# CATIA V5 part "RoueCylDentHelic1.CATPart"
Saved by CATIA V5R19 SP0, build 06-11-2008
Part number: Roue Cyl Denture Hélicoïdale
Bounding box of the stored display mesh (mm): x -74.504 to 74.497, y -74.496 to 74.494, z -20.617 to 50
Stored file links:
  G:\EU_thinkMotion\CFAO_2010\MMS_groupe2\MMS_groupe2\OK\melguidj\cfao_elguidj_2AMMSgrB\Modèle 3D\RoueCylDentHelic1.CATPart
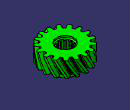
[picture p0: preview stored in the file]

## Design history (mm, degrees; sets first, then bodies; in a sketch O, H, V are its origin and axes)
External parameters (linked from other documents)
  External.Module = 7 mm
  External.Z = 17
  External.DiamPrimitif = 137.4094 mm {= External.ModuleApparent*External.Z}
  External.AnglePression = 20 deg
  External.x = 0
  External.DeportDenture = 0 mm {= External.x *External.ModuleApparent}
  External.DiamBase = 129.1226 mm {= External.DiamPrimitif *cos(External.AnglePression )}
  External.DiamPied = 119.9094 mm {= External.DiamPrimitif -2.5*External.Module +2*External.DeportDenture}
  External.DiamTete = 149 mm
  External.PhiPrimitif = 0.854 deg {= atan((sin(External.ThetaPrimitif*1rad)-External.ThetaPrimitif*cos(External.ThetaPrimitif*1rad))/(cos(External.ThetaPrimitif*1rad)+External.ThetaPrimitif*sin(External.ThetaPrimitif*1rad)))}
  External.PhiTete = 3.058 deg {= atan((sin(External.ThetaTete*1rad)-External.ThetaTete*cos(External.ThetaTete*1rad))/(cos(External.ThetaTete*1rad)+External.ThetaTete*sin(External.ThetaTete*1rad)))}
  External.PhiSymetrie = 5.2941 deg {= 180*1 deg/(2*External.Z )}
  External.CongePied = 2.66 mm {= 0.38*External.Module}
  External.AlphaCopie = 21.1765 deg {= 360*1 deg/External.Z}
  External.AlphaSymetrieCopie = 10.5882 deg {= External.AlphaCopie /2}
  External.LargeurDenture = 50 mm {= 50mm}
  External.ThetaPrimitif = 0.36397 {= sqrt(abs((External.DiamPrimitif*External.DiamPrimitif)/(External.DiamBase *External.DiamBase )-1))}
  External.ThetaTete = 0.575832 {= sqrt(abs((External.DiamTete*External.DiamTete)/(External.DiamBase *External.DiamBase )-1) )}
  External.Di = 133.266 mm {= (External.DiamBase +External.DiamPrimitif )/2}
  External.Thetai = 0.255358 {= sqrt(abs((External.Di*External.Di)/(External.DiamBase*External.DiamBase)-1))}
  External.Phii = 0.3061 deg {= atan((sin(External.Thetai*1rad)-External.Thetai*cos(External.Thetai*1rad))/(cos(External.Thetai*1rad)+External.Thetai*sin(External.Thetai*1rad)))}
  External.Dj = 143.2047 mm {= (External.DiamTete+External.DiamPrimitif)/2}
  External.Thetaj = 0.479598 {= sqrt(abs((External.Dj*External.Dj)/(External.DiamBase*External.DiamBase)-1))}
  External.Phij = 1.8567 deg {= atan((sin(External.Thetaj*1rad)-External.Thetaj*cos(External.Thetaj*1rad))/(cos(External.Thetaj*1rad)+External.Thetaj*sin(External.Thetaj*1rad)))}
  External.Dk = 131.1943 mm {= (External.Di+External.DiamBase)/2}
  External.Thetak = 0.179851 {= sqrt(abs((External.Dk*External.Dk)/(External.DiamBase*External.DiamBase)-1))}
  External.Phik = 0.109 deg {= atan((sin(External.Thetak*1rad)-External.Thetak*cos(External.Thetak*1rad))/(cos(External.Thetak*1rad)+External.Thetak*sin(External.Thetak*1rad)))}
  External.Dl = 135.3377 mm {= (External.DiamPrimitif+External.Di)/2}
  External.Thetal = 0.31398 {= sqrt(abs((External.Dl*External.Dl)/(External.DiamBase*External.DiamBase)-1))}
  External.Phil = 0.5585 deg {= atan((sin(External.Thetal*1rad)-External.Thetal*cos(External.Thetal*1rad))/(cos(External.Thetal*1rad)+External.Thetal*sin(External.Thetal*1rad)))}
  External.Dm = 140.307 mm {= (External.Dj+External.DiamPrimitif)/2}
  External.Thetam = 0.425136 {= sqrt(abs((External.Dm*External.Dm)/(External.DiamBase*External.DiamBase)-1))}
  External.Phim = 1.3264 deg {= atan((sin(External.Thetam*1rad)-External.Thetam*cos(External.Thetam*1rad))/(cos(External.Thetam*1rad)+External.Thetam*sin(External.Thetam*1rad)))}
  External.Dn = 146.1023 mm {= (External.DiamTete+External.Dj)/2}
  External.Thetan = 0.529429 {= sqrt(abs((External.Dn*External.Dn)/(External.DiamBase*External.DiamBase)-1))}
  External.Phin = 2.436 deg {= atan((sin(External.Thetan*1rad)-External.Thetan*cos(External.Thetan*1rad))/(cos(External.Thetan*1rad)+External.Thetan*sin(External.Thetan*1rad)))}
  External.AngleHelice = 30 deg
  External.ModuleApparent = 8.0829 mm {= External.Module /cos(External.AngleHelice )}
  External.SensDenture = -1
  External.LargeurDent = 45 mm {= round(PI*External.Module /sin(External.AngleHelice )/1mm)*1mm+1mm}
Body1 (main body)
  Sketch1 "EsquisseDent" on xy-plane, origin (0, 0, 0), H (1, 0, 0), V (0, 1, 0)
    construction circle A1 centre (0, 0) radius 68.7047
    construction circle A2 centre (0, 0) radius 64.5613
    construction circle A3 centre (0, 0) radius 59.9547
    construction circle A4 centre (0, 0) radius 74.5
    point P1 (64.5613, 0)
    construction line L1 (64.5613, 0) -> (0, 0)
    point P2 (68.6971, 1.024)
    construction line L2 (68.6971, 1.024) -> (0, 0)
    point P3 (74.3939, 3.9744)
    construction line L3 (74.3939, 3.9744) -> (0, 0)
    construction line L4 (64.5613, 0) -> (64.5613, 3.9367)
    point P4 (64.5613, 0)
    point P6 (60.4255, 1.024)
    construction line L5 (74.3939, 3.9744) -> (68.6971, 1.024)
    point P7 (71.5455, 2.4992)
    point P8 (57.5771, 2.4992)
    spline S1 through (57.5771, 2.4992) (60.4255, 1.024) (64.5613, 0) (65.597, 0.1248) (66.632, 0.356) (67.6656, 0.6596) (68.6971, 1.024) (70.1347, 1.6239) (71.5648, 2.3199) (72.9852, 3.1049) (74.3939, 3.9744)
    construction line L6 (0, 0) -> (5.2441, 0.5649)
    spline S2 through (56.7885, 9.82) (59.2574, 11.868) (63.0802, 13.7493) (64.1188, 13.8479) (65.1793, 13.8424) (66.2538, 13.7659) (67.3392, 13.6296) (68.8717, 13.3496) (70.4171, 12.9741) (71.9721, 12.5096) (73.5337, 11.9601)
    arc A5 centre (62.5641, -2.5174) radius 2.66 from (63.0483, 0.0982) to (59.9062, -2.4104) ccw
    point P11 (59.9062, -2.4104)
    arc A6 centre (0, 0) radius 74.5 from (74.3939, 3.9744) to (73.5337, 11.9601) ccw
    point P13 (73.5337, 11.9601)
    arc A7 centre (60.5927, 15.7836) radius 2.66 from (58.0186, 15.113) to (61.6229, 13.3311) ccw
    point P15 (58.0186, 15.113)
    construction line L7 (0, 0) -> (4.1018, 1.2334)
    construction line L8 (0, 0) -> (5.1105, -0.3968)
    point P19 (57.415, 17.265)
    arc A8 centre (0, 0) radius 59.9547 from (58.0186, 15.113) to (57.415, 17.265) ccw
    point P20 (59.7747, -4.6416)
    arc A9 centre (0, 0) radius 59.9547 from (59.7747, -4.6416) to (59.9062, -2.4104) ccw
    line L9 (57.415, 17.265) -> (0, 0)
    line L10 (59.7747, -4.6416) -> (0, 0)
    construction circle A10 centre (0, 0) radius 66.633
    construction line L11 (0, 0) -> (2.5698, 0.0137)
    point P22 (66.632, 0.356)
    construction circle A11 centre (0, 0) radius 71.6023
    construction line L12 (0, 0) -> (4.017, 0.1302)
    point P24 (71.5648, 2.3199)
    point P25 (71.5648, 2.3199)
    point P26 (70.4171, 12.9741)
    point P27 (65.1793, 13.8424)
    construction circle A12 centre (0, 0) radius 65.5971
    construction line L13 (0, 0) -> (48.2618, 0.0918)
    point P29 (64.1188, 13.8479)
    construction line L14 (0, 0) -> (63.6105, 6.852)
    point P31 (65.597, 0.1248)
    construction circle A13 centre (0, 0) radius 67.6688
    construction line L15 (0, 0) -> (57.3607, 0.5591)
    point P33 (67.6656, 0.6596)
    point P34 (66.2538, 13.7659)
    construction circle A14 centre (0, 0) radius 70.1535
    construction line L16 (0, 0) -> (65.6931, 1.5211)
    point P36 (70.1347, 1.6239)
    point P37 (68.8717, 13.3496)
    construction circle A15 centre (0, 0) radius 73.0512
    axis line L17 (0, 0) -> (59.2973, 2.5226)
    point P39 (71.9721, 12.5096)
    point P40 (72.9852, 3.1049)
    point P42 (57.5771, 2.4992)
    point P43 (60.4255, 1.024)
    point P44 (64.5613, 0)
    point P45 (68.6971, 1.024)
    point P46 (74.3939, 3.9744)
    point P47 (73.5337, 11.9601)
    point P48 (56.7885, 9.82)
    point P49 (67.3392, 13.6296)
    point P50 (63.0802, 13.7493)
    point P51 (59.2574, 11.868)
    point P52 (66.632, 0.356)
    point P53 (71.5648, 2.3199)
    point P54 (65.1793, 13.8424)
    point P55 (70.4171, 12.9741)
    point P56 (65.597, 0.1248)
    point P57 (64.1188, 13.8479)
    point P58 (67.6656, 0.6596)
    point P59 (66.2538, 13.7659)
    point P60 (70.1347, 1.6239)
    point P61 (68.8717, 13.3496)
    point P62 (72.9852, 3.1049)
    point P63 (71.9721, 12.5096)
    radius A1 = 68.7047 {= External.DiamPrimitif /2}
    radius A2 = 64.5613 {= External.DiamBase /2}
    radius A3 = 59.9547 {= External.DiamPied /2}
    radius A4 = 74.5 {= External.DiamTete /2}
    angle L2 L1 = 0.854 {= External.PhiPrimitif}
    angle L3 L1 = 3.058 {= External.PhiTete}
    angle L4 L1 = 90
    radius A5 = 2.66 {= External.CongePied}
    radius A7 = 2.66 {= External.CongePied}
    angle L7 L6 = 10.5882 {= External.AlphaSymetrieCopie}
    angle L2 L6 = 5.2941 {= External.PhiSymetrie}
    radius A10 = 66.633 {= External.Di /2}
    angle L11 L1 = 0.3061 {= External.Phii}
    radius A11 = 71.6023 {= External.Dj /2}
    angle L12 L1 = 1.8567 {= External.Phij}
    radius A12 = 65.5971 {= External.Dk/2}
    angle L13 L1 = 0.109 {= External.Phik}
    angle L14 L2 = 5.2941 {= External.PhiSymetrie}
    radius A13 = 67.6688 {= External.Dl /2}
    angle L15 L1 = 0.5585 {= External.Phil}
    radius A14 = 70.1535 {= External.Dm /2}
    angle L16 L1 = 1.3264 {= External.Phim}
    radius A15 = 73.0512 {= External.Dn/2}
    angle L17 L1 = 2.436 {= External.Phin}
    coincidence: P1 A2, P1 H, P2 A1, P3 A4, P4 A2, P7 L5, P42 P8, P43 P6, P44 P1, P45 L5, P45 L2, P46 L5, P46 L3, P11 A3, P47 P13, P15 A3, P19 L7, P19 A3, P20 L8, P20 A3, P3 P46, P22 L11, P22 A10, P52 P22, P24 L12, P24 A11, P53 P24, P25 P53, P54 P27, P55 P26, P31 L13, P31 A12, P56 P31, P57 P29, P33 L15, P33 A13, P58 P33, P59 P34, P36 L16, P36 A14, P60 P36, P61 P37, P40 L17, P40 A15, P62 P40, P63 P39, O L9, O L10
    horizontal: L1 H
    tangency: L4 A2, A5 A3, A5 S1, A7 A3, A7 S2, A8 A5, A9 A5
    symmetry: P6 P2 L4, P8 P7 L4, P46 P47 L6, P42 P48 L6, P45 P49 L6, P44 P50 L6, P43 P51 L6, L8 L7 L6, P26 P25 L6, P27 P22 L6, P29 P31 L14, P34 P33 L14, P37 P36 L14, P39 P40 L14
    midpoint: P7 L5
    parallelism: L9 L7, L10 L8
    concentricity: A10 A2, A11 A1
  Translate1: ToTransfor Sketch1, Direction (0, 0, 1), Length 50 {= External.LargeurDenture}
  Rotate1: ToTransfor Translate1, Axis Z axis, Angle -22.7906 {= External.SensDenture *atan(2*External.LargeurDenture/External.DiamPrimitif*tan(External.AngleHelice))}
  Translate2: ToTransfor Sketch1, Direction (0, 0, 1), Length 25 {= External.LargeurDenture/2}
  Rotate2: ToTransfor Translate2, Axis Z axis, Angle -11.8644 {= External.SensDenture *atan(External.LargeurDenture/(External.DiamPrimitif)*tan(External.AngleHelice))}
  Translate3: ToTransfor Sketch1, Direction (0, 0, 1), Length 37.5 {= 3/4*External.LargeurDenture}
  Rotate3: ToTransfor Translate3, Axis Z axis, Angle -17.491 {= External.SensDenture*atan(3*External.LargeurDenture/(2*External.DiamPrimitif)*tan(External.AngleHelice))}
  Translate4: ToTransfor Sketch1, Direction (0, 0, 1), Length 12.5 {= External.LargeurDenture/4}
  Rotate4: ToTransfor Translate4, Axis Z axis, Angle -5.9965 {= External.SensDenture*atan(External.LargeurDenture/(2*External.DiamPrimitif)*tan(External.AngleHelice))}
  Loft1: solid, Sections (Sketch1; Rotate4; Rotate2; Rotate3; Rotate1)
  CircPattern1: of the body so far, instances 17 {= External.Z}, angular step 21.1765 {= External.AlphaCopie}, axis from Z axis
  Plane1: type Offset, RefPlane xy-plane, Offset 50 {= External.LargeurDenture}, reversed
  Sketch2 on Plane1, origin (0, 0, -50), H (1, 0, 0), V (0, 1, 0)
    circle A1 centre (0, 0) radius 29
    radius A1 = 29 {= int(External.DiamPied/(4mm))*1mm}
  Pocket1: profile Sketch2, direction (0, 0, 1), length 150 {= 3*External.LargeurDenture}
  DatumCurve1
  DatumCurve2
  Plane2: stored without definition
  Plane3: stored without definition
  Sketch3 on yz-plane, origin (0, 0, 0), H (0, 1, 0), V (0, 0, 1)
    point P1 (29, 0)
    line L1 (29, 0) -> (42.5, 0)
    line L2 (42.5, 0) -> (42.5, -20.6171)
    line L3 (42.5, -20.6171) -> (29, -20.6171)
    point P3 (42.5, -20.6171)
    point P5 (42.5, -20.6171)
    reference intersected line E1 (74.5, 0) -> (-59.9547, 0) from face of CircPattern1
    line L4 (29, -20.6171) -> (29, 0)
    point P6 (29, 0)
    horizontal: L1 H, L3 H
    vertical: L2 V, L4 V
    fix: P5, P6
    coincidence: P3 P5, L1 E1, P1 P6
  Shaft1: profile Sketch3, axis edge of DatumCurve2, angle 360
  DatumCurve3
  DatumCurve4
  DatumSurface1
  DatumCurve5
  Plane4: stored without definition
  DatumCurve6 to DatumCurve9
  Sketch4 on zx-plane, origin (0, 0, 0), H (-1, 0, 0), V (0, 0, 1)
    point P1 (29, 45)
    line L1 (29, 45) -> (25, 42.6906)
    line L2 (25, 42.6906) -> (25, -13.6889)
    line L3 (25, -13.6889) -> (29, -20.6171)
    point P4 (29, -20.6171)
    line L4 (29, -20.6171) -> (29, 45)
    point P5 (29, 0)
    reference intersected line E1 through (0, -20.6171) direction (1, 0) from face of Shaft1 from Sketch3.L3
    reference projected line E2 (0, 412.703) -> (0, -326.9047) from edge of DatumCurve8
    reference intersected line E3 (-70.9575, 50) -> (65.4965, 50) from face of CircPattern1
    distance L2 E2 = 25
    angle L1 L4 = 60
    angle L3 L4 = 30
    distance P1 E3 = 5
    vertical: L4 V, L2 V
    fix: P5
    coincidence: P5 L4, P4 E1
  Shaft2: profile Sketch4, axis edge of DatumCurve9, angle 360
  Sketch5 on xy-plane, origin (0, 0, 0), H (1, 0, 0), V (0, 1, 0)
    circle A1 centre (0, 0) radius 25
    point P1 (-12.9191, 21.4032)
    point P2 (-12.9191, 21.4032)
    arc A2 centre (0, 0) radius 20.1556 from (19.3636, 5.5947) to (18.4145, 8.195) ccw
    point P3 (19.3636, 5.5947)
    point P4 (18.4145, 8.195)
    arc A3 centre (0, 0) radius 20.1556 from (19.9475, 2.8889) to (19.3636, 5.5947) ccw
    point P5 (19.9475, 2.8889)
    point P6 (19.3636, 5.5947)
    line L1 (19.9475, 2.8889) -> (23.9468, 2.9667)
    point P7 (19.9475, 2.8889)
    point P8 (23.9468, 2.9667)
    line L2 (23.9468, 2.9667) -> (24.0441, -2.0323)
    point P9 (23.9468, 2.9667)
    point P10 (24.0441, -2.0323)
    line L3 (24.0441, -2.0323) -> (20.0449, -2.1102)
    point P11 (24.0441, -2.0323)
    point P12 (20.0449, -2.1102)
    arc A4 centre (0, 0) radius 20.1556 from (19.5667, -4.8367) to (20.0449, -2.1102) ccw
    point P13 (19.5667, -4.8367)
    point P14 (20.0449, -2.1102)
    arc A5 centre (0, 0) radius 20.1556 from (18.7195, -7.4719) to (19.5667, -4.8367) ccw
    point P15 (18.7195, -7.4719)
    point P16 (19.5667, -4.8367)
    line L4 (22.2219, -9.4041) -> (18.7195, -7.4719)
    point P17 (22.2219, -9.4041)
    point P18 (18.7195, -7.4719)
    line L5 (19.8067, -13.7821) -> (22.2219, -9.4041)
    point P19 (19.8067, -13.7821)
    point P20 (22.2219, -9.4041)
    line L6 (16.3043, -11.8499) -> (19.8067, -13.7821)
    point P21 (16.3043, -11.8499)
    point P22 (19.8067, -13.7821)
    arc A6 centre (0, 0) radius 20.1556 from (14.5269, -13.972) to (16.3043, -11.8499) ccw
    point P23 (14.5269, -13.972)
    point P24 (16.3043, -11.8499)
    arc A7 centre (0, 0) radius 20.1556 from (12.4756, -15.8306) to (14.5269, -13.972) ccw
    point P25 (12.4756, -15.8306)
    point P26 (14.5269, -13.972)
    line L7 (12.4756, -15.8306) -> (14.5427, -19.2551)
    point P27 (12.4756, -15.8306)
    point P28 (14.5427, -19.2551)
    line L8 (14.5427, -19.2551) -> (10.262, -21.839)
    point P29 (14.5427, -19.2551)
    point P30 (10.262, -21.839)
    line L9 (10.262, -21.839) -> (8.195, -18.4145)
    point P31 (10.262, -21.839)
    point P32 (8.195, -18.4145)
    arc A8 centre (0, 0) radius 20.1556 from (5.5947, -19.3636) to (8.195, -18.4145) ccw
    point P33 (5.5947, -19.3636)
    point P34 (8.195, -18.4145)
    arc A9 centre (0, 0) radius 20.1556 from (2.8889, -19.9475) to (5.5947, -19.3636) ccw
    point P35 (2.8889, -19.9475)
    point P36 (5.5947, -19.3636)
    line L10 (2.9667, -23.9468) -> (2.8889, -19.9475)
    point P37 (2.9667, -23.9468)
    point P38 (2.8889, -19.9475)
    line L11 (-2.0323, -24.0441) -> (2.9667, -23.9468)
    point P39 (-2.0323, -24.0441)
    point P40 (2.9667, -23.9468)
    line L12 (-2.1102, -20.0449) -> (-2.0323, -24.0441)
    point P41 (-2.1102, -20.0449)
    point P42 (-2.0323, -24.0441)
    arc A10 centre (0, 0) radius 20.1556 from (-4.8367, -19.5667) to (-2.1102, -20.0449) ccw
    point P43 (-4.8367, -19.5667)
    point P44 (-2.1102, -20.0449)
    arc A11 centre (0, 0) radius 20.1556 from (-7.4719, -18.7195) to (-4.8367, -19.5667) ccw
    point P45 (-7.4719, -18.7195)
    point P46 (-4.8367, -19.5667)
    line L13 (-7.4719, -18.7195) -> (-9.4041, -22.2219)
    point P47 (-7.4719, -18.7195)
    point P48 (-9.4041, -22.2219)
    line L14 (-9.4041, -22.2219) -> (-13.7821, -19.8067)
    point P49 (-9.4041, -22.2219)
    point P50 (-13.7821, -19.8067)
    line L15 (-13.7821, -19.8067) -> (-11.8499, -16.3043)
    point P51 (-13.7821, -19.8067)
    point P52 (-11.8499, -16.3043)
    arc A12 centre (0, 0) radius 20.1556 from (-13.972, -14.5269) to (-11.8499, -16.3043) ccw
    point P53 (-13.972, -14.5269)
    point P54 (-11.8499, -16.3043)
    arc A13 centre (0, 0) radius 20.1556 from (-15.8306, -12.4756) to (-13.972, -14.5269) ccw
    point P55 (-15.8306, -12.4756)
    point P56 (-13.972, -14.5269)
    line L16 (-19.2551, -14.5427) -> (-15.8306, -12.4756)
    point P57 (-19.2551, -14.5427)
    point P58 (-15.8306, -12.4756)
    line L17 (-21.839, -10.262) -> (-19.2551, -14.5427)
    point P59 (-21.839, -10.262)
    point P60 (-19.2551, -14.5427)
    line L18 (-18.4145, -8.195) -> (-21.839, -10.262)
    point P61 (-18.4145, -8.195)
    point P62 (-21.839, -10.262)
    arc A14 centre (0, 0) radius 20.1556 from (-19.3636, -5.5947) to (-18.4145, -8.195) ccw
    point P63 (-19.3636, -5.5947)
    point P64 (-18.4145, -8.195)
    arc A15 centre (0, 0) radius 20.1556 from (-19.9475, -2.8889) to (-19.3636, -5.5947) ccw
    point P65 (-19.9475, -2.8889)
    point P66 (-19.3636, -5.5947)
    line L19 (-19.9475, -2.8889) -> (-23.9468, -2.9667)
    point P67 (-19.9475, -2.8889)
    point P68 (-23.9468, -2.9667)
    line L20 (-23.9468, -2.9667) -> (-24.0441, 2.0323)
    point P69 (-23.9468, -2.9667)
    point P70 (-24.0441, 2.0323)
    line L21 (-24.0441, 2.0323) -> (-20.0449, 2.1102)
    point P71 (-24.0441, 2.0323)
    point P72 (-20.0449, 2.1102)
    arc A16 centre (0, 0) radius 20.1556 from (-19.5667, 4.8367) to (-20.0449, 2.1102) ccw
    point P73 (-19.5667, 4.8367)
    point P74 (-20.0449, 2.1102)
    arc A17 centre (0, 0) radius 20.1556 from (-18.7195, 7.4719) to (-19.5667, 4.8367) ccw
    point P75 (-18.7195, 7.4719)
    point P76 (-19.5667, 4.8367)
    line L22 (-22.2219, 9.4041) -> (-18.7195, 7.4719)
    point P77 (-22.2219, 9.4041)
    point P78 (-18.7195, 7.4719)
    line L23 (-19.8067, 13.7821) -> (-22.2219, 9.4041)
    point P79 (-19.8067, 13.7821)
    point P80 (-22.2219, 9.4041)
    line L24 (-16.3043, 11.8499) -> (-19.8067, 13.7821)
    point P81 (-16.3043, 11.8499)
    point P82 (-19.8067, 13.7821)
    arc A18 centre (0, 0) radius 20.1556 from (-14.5269, 13.972) to (-16.3043, 11.8499) ccw
    point P83 (-14.5269, 13.972)
    point P84 (-16.3043, 11.8499)
    arc A19 centre (0, 0) radius 20.1556 from (-12.4756, 15.8306) to (-14.5269, 13.972) ccw
    point P85 (-12.4756, 15.8306)
    point P86 (-14.5269, 13.972)
    line L25 (-12.4756, 15.8306) -> (-14.5427, 19.2551)
    point P87 (-12.4756, 15.8306)
    point P88 (-14.5427, 19.2551)
    line L26 (-14.5427, 19.2551) -> (-10.262, 21.839)
    point P89 (-14.5427, 19.2551)
    point P90 (-10.262, 21.839)
    line L27 (-10.262, 21.839) -> (-8.195, 18.4145)
    point P91 (-10.262, 21.839)
    point P92 (-8.195, 18.4145)
    arc A20 centre (0, 0) radius 20.1556 from (-5.5947, 19.3636) to (-8.195, 18.4145) ccw
    point P93 (-5.5947, 19.3636)
    point P94 (-8.195, 18.4145)
    arc A21 centre (0, 0) radius 20.1556 from (-2.8889, 19.9475) to (-5.5947, 19.3636) ccw
    point P95 (-2.8889, 19.9475)
    point P96 (-5.5947, 19.3636)
    line L28 (-2.9667, 23.9468) -> (-2.8889, 19.9475)
    point P97 (-2.9667, 23.9468)
    point P98 (-2.8889, 19.9475)
    line L29 (2.0323, 24.0441) -> (-2.9667, 23.9468)
    point P99 (2.0323, 24.0441)
    point P100 (-2.9667, 23.9468)
    line L30 (2.1102, 20.0449) -> (2.0323, 24.0441)
    point P101 (2.1102, 20.0449)
    point P102 (2.0323, 24.0441)
    arc A22 centre (0, 0) radius 20.1556 from (4.8367, 19.5667) to (2.1102, 20.0449) ccw
    point P103 (4.8367, 19.5667)
    point P104 (2.1102, 20.0449)
    arc A23 centre (0, 0) radius 20.1556 from (7.4719, 18.7195) to (4.8367, 19.5667) ccw
    point P105 (7.4719, 18.7195)
    point P106 (4.8367, 19.5667)
    line L31 (7.4719, 18.7195) -> (9.4041, 22.2219)
    point P107 (7.4719, 18.7195)
    point P108 (9.4041, 22.2219)
    line L32 (9.4041, 22.2219) -> (13.7821, 19.8067)
    point P109 (9.4041, 22.2219)
    point P110 (13.7821, 19.8067)
    line L33 (13.7821, 19.8067) -> (11.8499, 16.3043)
    point P111 (13.7821, 19.8067)
    point P112 (11.8499, 16.3043)
    arc A24 centre (0, 0) radius 20.1556 from (13.972, 14.5269) to (11.8499, 16.3043) ccw
    point P113 (13.972, 14.5269)
    point P114 (11.8499, 16.3043)
    arc A25 centre (0, 0) radius 20.1556 from (15.8306, 12.4756) to (13.972, 14.5269) ccw
    point P115 (15.8306, 12.4756)
    point P116 (13.972, 14.5269)
    line L34 (19.2551, 14.5427) -> (15.8306, 12.4756)
    point P117 (19.2551, 14.5427)
    point P118 (15.8306, 12.4756)
    line L35 (21.839, 10.262) -> (19.2551, 14.5427)
    point P119 (21.839, 10.262)
    point P120 (19.2551, 14.5427)
    line L36 (18.4145, 8.195) -> (21.839, 10.262)
    point P121 (18.4145, 8.195)
    point P122 (21.839, 10.262)
    coincidence: P1 P2, P3 P6, P4 P121, P5 P7, P8 P9, P10 P11, P12 P14, P13 P16, P15 P18, P17 P20, P19 P22, P21 P24, P23 P26, P25 P27, P28 P29, P30 P31, P32 P34, P33 P36, P35 P38, P37 P40, P39 P42, P41 P44, P43 P46, P45 P47, P48 P49, P50 P51, P52 P54, P53 P56, P55 P58, P57 P60, P59 P62, P61 P64, P63 P66, P65 P67, P68 P69, P70 P71, P72 P74, P73 P76, P75 P78, P77 P80, P79 P82, P81 P84, P83 P86, P85 P87, P88 P89, P90 P91, P92 P94, P93 P96, P95 P98, P97 P100, P99 P102, P101 P104, P103 P106, P105 P107, P108 P109, P110 P111, P112 P114, P113 P116, P115 P118, P117 P120, P119 P122
  Pad1: profile Sketch5, direction (0, 0, -1), length 13.689, opposite side length 42.691
  DatumCurve10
